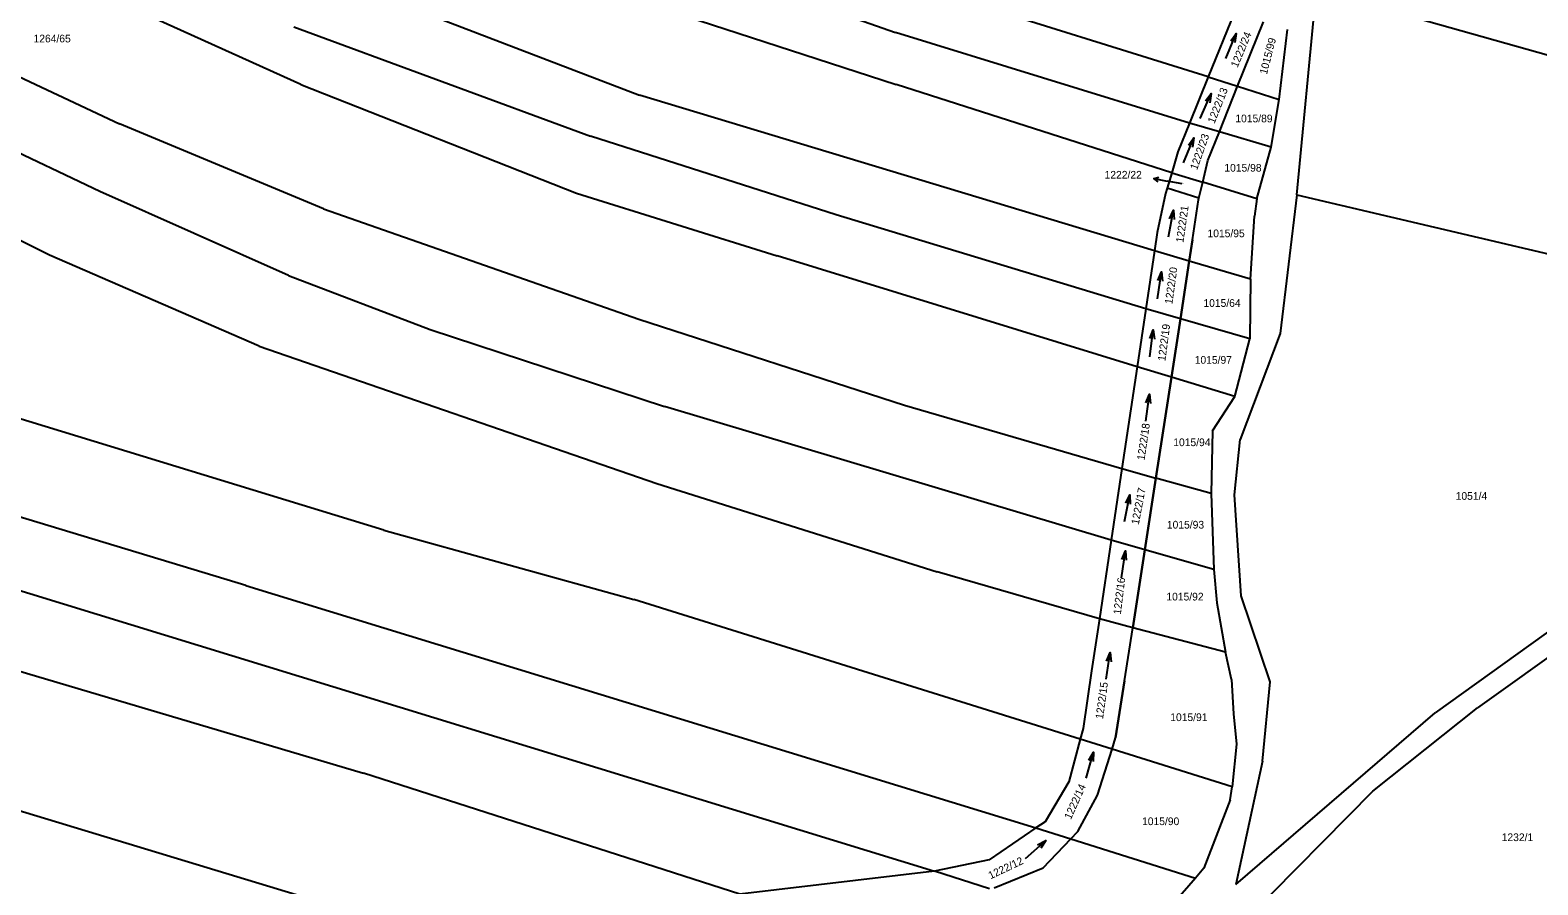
# Model space of a CAD drawing. Extents: x -777309 to -774195, y -1144706 to -1143600.
# Drawn here: x -776384.4 to -776051.5, y -1144455.3 to -1144266.5 of the extents above; entities that cross this region are included whole.
import ezdxf

# ---------------------------------------------------------------- set-up
doc = ezdxf.new("R2010")
doc.units = 0
for name, color, linetype in [('1', 7, 'Continuous'), ('11', 7, 'Continuous'), ('2', 7, 'Continuous'), ('3', 7, 'Continuous'), ('7', 7, 'Continuous')]:
    doc.layers.add(name, color=color, linetype=linetype)

msp = doc.modelspace()

# ---------------------------------------------------------------- linework, layer by layer
at = {"layer": '1'}
for p, q in [((-776463.39, -1144240.71), (-776364.66, -1144287.25)), ((-776263.02, -1144242.23), (-776193.31, -1144267.08)), ((-776124.24, -1144276.84), (-776206.49, -1144251.17)), ((-776322.84, -1144252.89), (-776249.8, -1144280.91)), ((-776324.6, -1144278.51), (-776377.44, -1144254.65)), ((-776104.65, -1144302.9), (-776100.36, -1144257.59)), ((-776100.36, -1144257.59), (-775964.86, -1144295.82)), ((-776369.01, -1144302.14), (-776451.08, -1144263.13)), ((-776239.59, -1144263.48), (-776193.18, -1144278.57)), ((-776118.46, -1144262.59), (-776124.24, -1144276.84)), ((-776326.16, -1144265.8), (-776260.62, -1144289.93)), ((-776128.39, -1144287.08), (-776193.31, -1144267.08)), ((-776117.76, -1144278.93), (-776112.06, -1144264.67)), ((-776108.61, -1144281.88), (-776106.75, -1144266.4)), ((-776124.24, -1144276.84), (-776128.39, -1144287.08)), ((-776124.24, -1144276.84), (-776117.76, -1144278.93)), ((-776324.6, -1144278.51), (-776263.77, -1144302.5)), ((-776136.12, -1144315.24), (-776249.8, -1144280.91)), ((-776132.3, -1144298.01), (-776193.18, -1144278.57)), ((-776121.79, -1144289.01), (-776117.76, -1144278.93)), ((-776117.76, -1144278.93), (-776108.61, -1144281.88)), ((-776380.08, -1144316.22), (-776443.83, -1144284.45)), ((-776110.36, -1144292.35), (-776108.61, -1144281.88)), ((-776319.63, -1144305.99), (-776364.66, -1144287.25)), ((-776128.39, -1144287.08), (-776130.95, -1144293.39)), ((-776121.79, -1144289.01), (-776128.39, -1144287.08)), ((-776206.39, -1144307.32), (-776260.62, -1144289.93)), ((-776124.31, -1144295.31), (-776121.79, -1144289.01)), ((-776110.36, -1144292.35), (-776121.79, -1144289.01)), ((-776130.95, -1144293.39), (-776132.3, -1144298.01)), ((-776113.49, -1144303.76), (-776110.36, -1144292.35)), ((-776125.47, -1144300.13), (-776124.31, -1144295.31)), ((-776132.3, -1144298.01), (-776133.31, -1144301.45)), ((-776132.3, -1144298.01), (-776125.47, -1144300.13)), ((-776126.32, -1144303.67), (-776125.47, -1144300.13)), ((-776113.49, -1144303.76), (-776125.47, -1144300.13)), ((-776327.31, -1144320.71), (-776369.01, -1144302.14)), ((-776263.77, -1144302.5), (-776219.46, -1144316.38)), ((-776133.66, -1144302.64), (-776135.52, -1144311.24)), ((-776133.31, -1144301.45), (-776133.66, -1144302.64)), ((-776126.32, -1144303.67), (-776133.31, -1144301.45)), ((-776127.71, -1144312.84), (-776126.41, -1144304.03)), ((-776126.41, -1144304.03), (-776126.32, -1144303.67)), ((-776113.49, -1144303.76), (-776114.03, -1144307.59)), ((-776104.65, -1144302.9), (-776108.4, -1144333.55)), ((-776104.65, -1144302.9), (-775974.56, -1144333.51)), ((-776319.63, -1144305.99), (-776249.99, -1144330.39)), ((-776138.04, -1144328.07), (-776206.39, -1144307.32)), ((-776114.9, -1144321.56), (-776114.03, -1144307.59)), ((-776135.52, -1144311.24), (-776136.12, -1144315.24)), ((-776127.71, -1144312.84), (-776128.43, -1144317.53)), ((-776333.82, -1144336.34), (-776380.08, -1144316.22)), ((-776139.95, -1144340.89), (-776219.46, -1144316.38)), ((-776136.12, -1144315.24), (-776138.04, -1144328.07)), ((-776128.43, -1144317.53), (-776136.12, -1144315.24)), ((-776128.43, -1144317.53), (-776130.4, -1144330.27)), ((-776114.9, -1144321.56), (-776128.43, -1144317.53)), ((-776327.31, -1144320.71), (-776296.05, -1144332.67)), ((-776114.9, -1144321.56), (-776115.03, -1144334.7)), ((-776249.99, -1144330.39), (-776191.33, -1144349.34)), ((-776138.04, -1144328.07), (-776139.95, -1144340.89)), ((-776130.4, -1144330.27), (-776138.04, -1144328.07)), ((-776130.4, -1144330.27), (-776132.39, -1144343.18)), ((-776115.03, -1144334.7), (-776130.4, -1144330.27)), ((-776296.05, -1144332.67), (-776244.27, -1144349.66)), ((-776108.4, -1144333.55), (-776117.19, -1144356.92)), ((-776333.82, -1144336.34), (-776245.97, -1144366.65)), ((-776118.37, -1144347.43), (-776115.03, -1144334.7)), ((-776306.29, -1144376.93), (-776433.42, -1144338.06)), ((-776139.95, -1144340.89), (-776143.31, -1144363.37)), ((-776132.39, -1144343.18), (-776139.95, -1144340.89)), ((-776336.73, -1144389.18), (-776488.73, -1144343.19)), ((-776132.39, -1144343.18), (-776135.83, -1144365.45)), ((-776118.37, -1144347.43), (-776132.39, -1144343.18)), ((-776123.29, -1144355.01), (-776118.37, -1144347.43)), ((-776145.67, -1144379.15), (-776244.27, -1144349.66)), ((-776191.33, -1144349.34), (-776143.31, -1144363.37)), ((-776123.29, -1144355.01), (-776123.58, -1144368.89)), ((-776118.42, -1144369.14), (-776117.19, -1144356.92)), ((-776143.31, -1144363.37), (-776145.67, -1144379.15)), ((-776143.31, -1144363.37), (-776135.83, -1144365.45)), ((-776245.97, -1144366.65), (-776184.13, -1144386.14)), ((-776135.83, -1144365.45), (-776138.27, -1144381.26)), ((-776123.58, -1144368.89), (-776135.83, -1144365.45)), ((-776123.58, -1144368.89), (-776123.01, -1144385.62)), ((-776116.98, -1144391.49), (-776118.42, -1144369.14)), ((-776306.29, -1144376.93), (-776251.08, -1144392.3)), ((-776145.67, -1144379.15), (-776148.27, -1144396.56)), ((-776138.27, -1144381.26), (-776145.67, -1144379.15)), ((-776406.48, -1144384.18), (-776184.7, -1144452.28)), ((-776138.27, -1144381.26), (-776140.93, -1144398.49)), ((-776123.01, -1144385.62), (-776138.27, -1144381.26)), ((-776024.08, -1144381.29), (-776074.15, -1144417.28)), ((-776148.27, -1144396.56), (-776184.13, -1144386.14)), ((-776123.01, -1144385.62), (-776122.36, -1144392.98)), ((-776336.73, -1144389.18), (-776162.3, -1144442.71)), ((-776152.53, -1144423.14), (-776251.08, -1144392.3)), ((-776122.36, -1144392.98), (-776120.46, -1144403.86)), ((-776110.57, -1144410.43), (-776116.98, -1144391.49)), ((-776148.27, -1144396.56), (-776149.99, -1144408.05)), ((-776140.93, -1144398.49), (-776148.27, -1144396.56)), ((-776038.99, -1144397.74), (-776064.78, -1144416.16)), ((-776142.75, -1144410.24), (-776140.93, -1144398.49)), ((-776120.46, -1144403.86), (-776140.93, -1144398.49)), ((-776402.77, -1144403.36), (-776310.77, -1144430.59)), ((-776119.14, -1144409.91), (-776120.46, -1144403.86)), ((-776149.99, -1144408.05), (-776151.89, -1144420.73)), ((-776142.75, -1144410.24), (-776144.7, -1144422.84)), ((-776119.14, -1144409.91), (-776118.65, -1144417.52)), ((-776112.29, -1144427.95), (-776110.57, -1144410.43)), ((-776471.4, -1144413.28), (-776297.5, -1144465.91)), ((-776118.65, -1144417.52), (-776117.99, -1144424.19)), ((-776118.18, -1144455.2), (-776074.15, -1144417.28)), ((-776087.91, -1144434.59), (-776064.78, -1144416.16)), ((-776151.89, -1144420.73), (-776152.53, -1144423.14)), ((-776152.53, -1144423.14), (-776155.03, -1144432.5)), ((-776145.49, -1144425.35), (-776152.53, -1144423.14)), ((-776145.49, -1144425.35), (-776144.7, -1144422.84)), ((-776117.99, -1144424.19), (-776119, -1144433.65)), ((-776148.69, -1144435.46), (-776145.49, -1144425.35)), ((-776119, -1144433.65), (-776145.49, -1144425.35)), ((-776227.64, -1144457.32), (-776310.77, -1144430.59)), ((-776112.29, -1144427.95), (-776118.18, -1144455.2)), ((-776155.03, -1144432.5), (-776160.29, -1144441.33)), ((-776119.4, -1144436.53), (-776119, -1144433.65)), ((-776153.02, -1144443.48), (-776148.69, -1144435.46)), ((-776087.91, -1144434.59), (-776132.08, -1144479.31)), ((-776119.4, -1144436.53), (-776125.19, -1144451.61)), ((-776162.3, -1144442.71), (-776172.59, -1144449.79)), ((-776160.29, -1144441.33), (-776162.3, -1144442.71)), ((-776162.3, -1144442.71), (-776154.59, -1144445.13)), ((-776154.59, -1144445.13), (-776153.02, -1144443.48)), ((-776160.7, -1144451.53), (-776154.59, -1144445.13)), ((-776154.59, -1144445.13), (-776127.07, -1144453.77)), ((-776172.59, -1144449.79), (-776184.7, -1144452.28)), ((-776184.7, -1144452.28), (-776227.64, -1144457.32)), ((-776172.56, -1144456.15), (-776184.7, -1144452.28)), ((-776171.5, -1144455.94), (-776160.7, -1144451.53)), ((-776127.07, -1144453.77), (-776138.57, -1144466.99)), ((-776125.19, -1144451.61), (-776127.07, -1144453.77))]:
    msp.add_line(p, q, dxfattribs=at)
at = {"layer": '11'}
for points in [[(-776118.46, -1144262.59), (-776124.24, -1144276.84), (-776128.39, -1144287.08), (-776130.95, -1144293.39), (-776132.3, -1144298.01), (-776133.31, -1144301.45), (-776133.66, -1144302.64), (-776135.52, -1144311.24), (-776136.12, -1144315.24), (-776138.04, -1144328.07), (-776139.95, -1144340.89), (-776143.31, -1144363.37), (-776145.67, -1144379.15), (-776148.27, -1144396.56), (-776149.99, -1144408.05), (-776151.89, -1144420.73), (-776152.53, -1144423.14), (-776155.03, -1144432.5), (-776160.29, -1144441.33), (-776162.3, -1144442.71), (-776172.59, -1144449.79), (-776184.7, -1144452.28), (-776227.64, -1144457.32)], [(-776171.5, -1144455.94), (-776160.7, -1144451.53), (-776154.59, -1144445.13), (-776153.02, -1144443.48), (-776148.69, -1144435.46), (-776145.49, -1144425.35), (-776144.7, -1144422.84), (-776142.75, -1144410.24), (-776140.93, -1144398.49), (-776138.27, -1144381.26), (-776135.83, -1144365.45), (-776132.39, -1144343.18), (-776130.4, -1144330.27), (-776128.43, -1144317.53), (-776127.71, -1144312.84), (-776126.41, -1144304.03), (-776126.32, -1144303.67), (-776125.47, -1144300.13), (-776124.31, -1144295.31), (-776121.79, -1144289.01), (-776117.76, -1144278.93), (-776112.06, -1144264.67)]]:
    msp.add_lwpolyline(points, dxfattribs=at)
at = {"layer": '3'}
for p, q in [((-776120.33, -1144272.79), (-776118.05, -1144267.25)), ((-776126.01, -1144286.01), (-776123.57, -1144280.53)), ((-776129.73, -1144295.84), (-776127.41, -1144290.3)), ((-776132.99, -1144312.2), (-776131.93, -1144306.3)), ((-776135.43, -1144325.86), (-776134.59, -1144319.92)), ((-776137.11, -1144338.69), (-776136.39, -1144332.73)), ((-776138.03, -1144352.86), (-776137.25, -1144346.92)), ((-776142.74, -1144375.04), (-776141.54, -1144369.16)), ((-776143.42, -1144387.45), (-776142.54, -1144381.51)), ((-776146.78, -1144409.88), (-776145.9, -1144403.94)), ((-776151.21, -1144431.75), (-776149.57, -1144425.97)), ((-776164.56, -1144449.49), (-776160.08, -1144445.51))]:
    msp.add_line(p, q, dxfattribs=at)
for points in [[(-776119.27, -1144268.9), (-776118.05, -1144267.25), (-776118.35, -1144269.29)], [(-776124.84, -1144282.15), (-776123.57, -1144280.53), (-776123.93, -1144282.56)], [(-776128.64, -1144291.95), (-776127.41, -1144290.3), (-776127.72, -1144292.34)], [(-776132.78, -1144308.18), (-776131.93, -1144306.3), (-776131.79, -1144308.35)], [(-776135.36, -1144321.83), (-776134.59, -1144319.92), (-776134.37, -1144321.97)], [(-776137.12, -1144334.66), (-776136.39, -1144332.73), (-776136.13, -1144334.78)], [(-776138, -1144348.83), (-776137.25, -1144346.92), (-776137.01, -1144348.96)], [(-776142.43, -1144371.02), (-776141.54, -1144369.16), (-776141.45, -1144371.22)], [(-776143.33, -1144383.42), (-776142.54, -1144381.51), (-776142.34, -1144383.56)], [(-776146.69, -1144405.85), (-776145.9, -1144403.94), (-776145.7, -1144406)], [(-776150.6, -1144427.76), (-776149.57, -1144425.97), (-776149.64, -1144428.03)], [(-776161.91, -1144446.46), (-776160.08, -1144445.51), (-776161.24, -1144447.21)]]:
    msp.add_lwpolyline(points, dxfattribs=at)
at = {"layer": '7'}
for p in [(-776136.23, -1144299.32), (-776130.02, -1144300.47)]:
    msp.add_line(p, (-776133.28, -1144299.87), dxfattribs=at)
msp.add_lwpolyline([(-776135.34, -1144300), (-776136.23, -1144299.32), (-776135.16, -1144299.01)], dxfattribs=at)

# ---------------------------------------------------------------- texts
at = {"layer": '2'}
for s, height, p in [('1264/65', 1.7, (-776383.62, -1144269.24)), ('1015/89', 1.7, (-776118.26, -1144286.89)), ('1015/98', 1.7, (-776120.69, -1144297.78)), ('1222/22', 0.1, (-776130, -1144300.47)), ('1015/95', 1.7, (-776124.41, -1144312.26)), ('1015/64', 1.7, (-776125.31, -1144327.64)), ('1015/97', 1.7, (-776127.23, -1144340.2)), ('1015/94', 1.7, (-776131.97, -1144358.4)), ('1051/4', 1.7, (-776069.61, -1144370.25)), ('1015/93', 1.7, (-776133.38, -1144376.6)), ('1015/92', 1.7, (-776133.49, -1144392.48)), ('1015/91', 1.7, (-776132.63, -1144419.11)), ('1015/90', 1.7, (-776138.86, -1144442.09)), ('1232/1', 1.7, (-776059.45, -1144445.62))]:
    msp.add_text(s, height=height, dxfattribs=at).set_placement(p)
for s, rotation, p in [('1222/24', 67.4944, (-776117.79, -1144274.95)), ('1015/99', 75.5158, (-776111.3, -1144276.43)), ('1222/13', 68.583, (-776122.87, -1144287.29)), ('1222/23', 70.5884, (-776126.72, -1144297.54)), ('1222/21', 81.8184, (-776129.74, -1144313.54)), ('1222/20', 82.0476, (-776132.18, -1144327.13)), ('1222/19', 82.4486, (-776133.72, -1144339.69)), ('1222/18', 81.5892, (-776138.32, -1144361.6)), ('1222/17', 79.1828, (-776139.59, -1144375.83)), ('1222/16', 83.0789, (-776143.55, -1144395.66)), ('1222/15', 82.2194, (-776147.48, -1144418.76)), ('1222/14', 65.7183, (-776154.58, -1144440.98)), ('1222/12', 25.382, (-776172.32, -1144454.08))]:
    msp.add_text(s, height=1.7, rotation=rotation, dxfattribs=at).set_placement(p)
at = {"layer": '7'}
msp.add_text('1222/22', height=1.7, dxfattribs=at).set_placement((-776147.13, -1144299.32))

doc.saveas('drawing.dxf')
